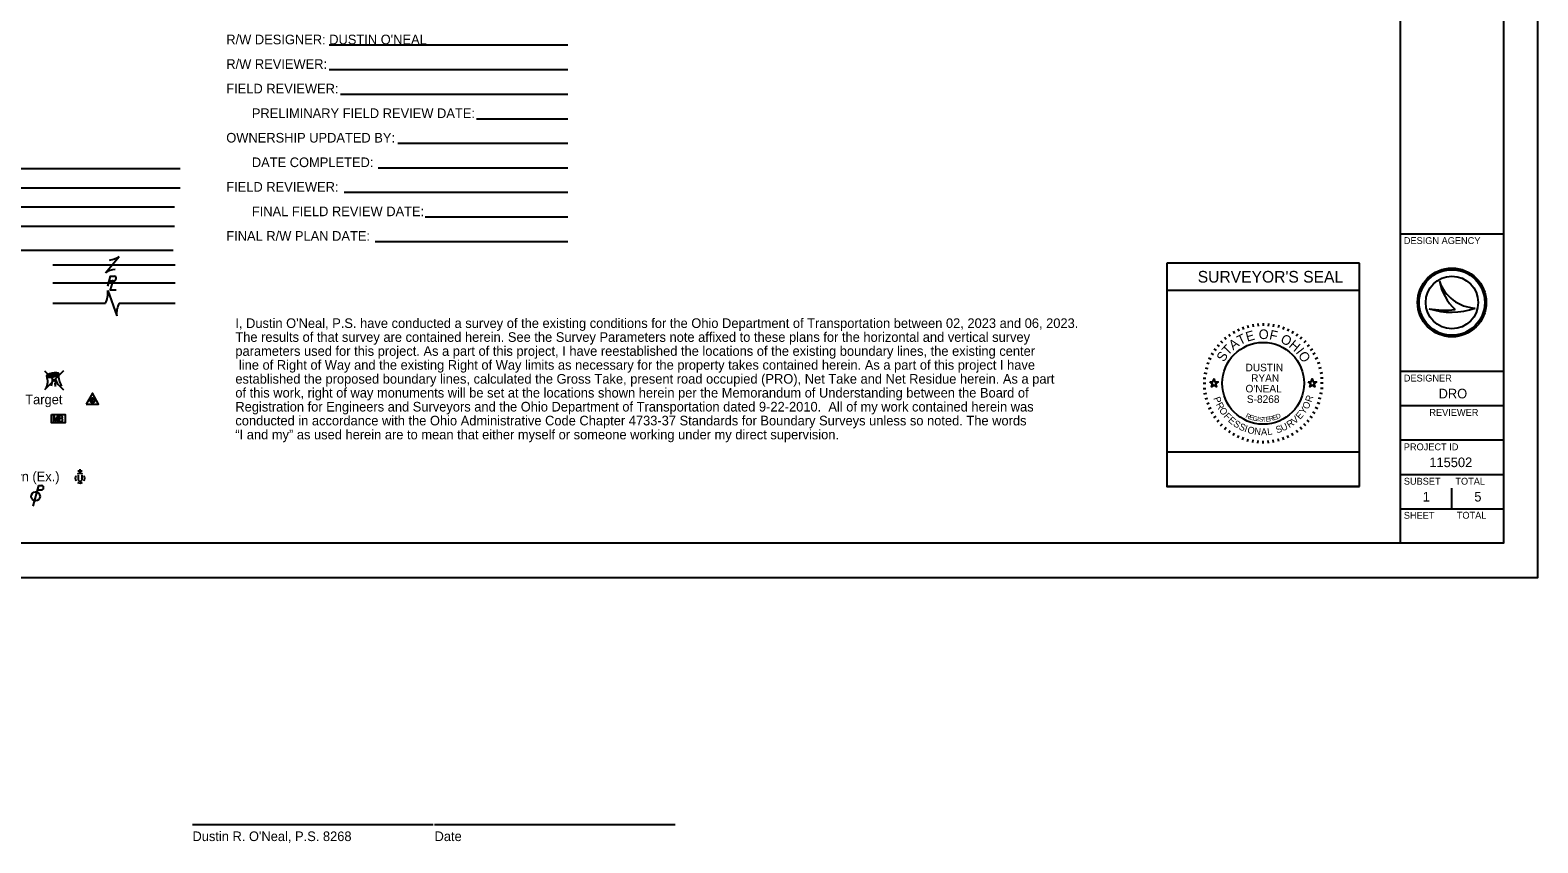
# Model space of a CAD drawing. Extents: x -11.1 to 34, y -3.9 to 22.
# Drawn here: x 12.07 to 34, y -3.86 to 7.96 of the extents above; entities that cross this region are included whole.
import ezdxf

# ---------------------------------------------------------------- set-up
doc = ezdxf.new("R2010")
doc.units = 0
for name, color, linetype in [('Default', 7, 'Continuous'), ('SH_Border', 7, 'Continuous'), ('SH_Cut_Line', 7, 'Continuous'), ('SH_Data', 7, 'Continuous'), ('SH_Text', 7, 'Continuous')]:
    doc.layers.add(name, color=color, linetype=linetype)

msp = doc.modelspace()

# ---------------------------------------------------------------- linework, layer by layer
at = {"layer": 'Default'}
for points in [[(29.227, 2.844), (29.274, 2.844), (29.289, 2.889), (29.303, 2.844), (29.35, 2.844), (29.312, 2.816), (29.327, 2.772), (29.289, 2.799), (29.251, 2.772), (29.265, 2.816)], [(30.657, 2.844), (30.704, 2.844), (30.719, 2.889), (30.733, 2.844), (30.78, 2.844), (30.742, 2.816), (30.757, 2.772), (30.719, 2.799), (30.681, 2.772), (30.695, 2.816)]]:
    msp.add_lwpolyline(points, close=True, dxfattribs=at)
at = {"layer": 'SH_Border'}
for p, q in [((32, 0.5), (32, 21.5)), ((32, 5), (33.5, 5)), ((32, 3), (33.5, 3)), ((32, 2.5), (33.5, 2.5)), ((32, 2), (33.5, 2)), ((32, 1.5), (33.5, 1.5)), ((32, 1), (33.5, 1))]:
    msp.add_line(p, q, dxfattribs=at)
msp.add_lwpolyline([(1.5, 21.5), (33.5, 21.5), (33.5, 0.5), (1.5, 0.5)], close=True, dxfattribs=at)
at = {"layer": 'SH_Cut_Line'}
msp.add_lwpolyline([(0, 0), (34, 0), (34, 22), (0, 22)], close=True, dxfattribs=at)
at = {"layer": 'SH_Data'}
for p, q in [((31.404, 4.574), (28.604, 4.574)), ((28.604, 4.574), (28.604, 1.324)), ((31.404, 1.324), (31.404, 4.574)), ((31.404, 4.174), (28.604, 4.174)), ((32.567, 4.31), (32.567, 4.31)), ((32.75, 4), (32.75, 4)), ((32.417, 3.91), (32.417, 3.91)), ((33.087, 3.919), (33.087, 3.919)), ((29.502, 3.541), (29.525, 3.508)), ((29.566, 3.582), (29.586, 3.547)), ((29.634, 3.617), (29.651, 3.581)), ((29.705, 3.646), (29.718, 3.609)), ((29.777, 3.669), (29.788, 3.631)), ((29.852, 3.686), (29.859, 3.646)), ((29.928, 3.696), (29.931, 3.656)), ((30.004, 3.699), (30.004, 3.659)), ((30.08, 3.696), (30.077, 3.656)), ((30.156, 3.686), (30.149, 3.646)), ((30.23, 3.669), (30.22, 3.631)), ((30.303, 3.646), (30.289, 3.609)), ((30.374, 3.617), (30.357, 3.581)), ((30.441, 3.582), (30.421, 3.547)), ((30.506, 3.541), (30.483, 3.508)), ((29.287, 3.326), (29.32, 3.303)), ((29.334, 3.386), (29.364, 3.361)), ((29.385, 3.443), (29.413, 3.414)), ((29.441, 3.494), (29.467, 3.464)), ((30.566, 3.494), (30.541, 3.464)), ((30.623, 3.443), (30.594, 3.414)), ((30.674, 3.386), (30.644, 3.361)), ((30.721, 3.326), (30.688, 3.303)), ((29.182, 3.123), (29.219, 3.11)), ((29.211, 3.194), (29.247, 3.177)), ((29.246, 3.262), (29.281, 3.242)), ((30.762, 3.262), (30.727, 3.242)), ((30.797, 3.194), (30.761, 3.177)), ((30.826, 3.123), (30.789, 3.11)), ((29.132, 2.9), (29.172, 2.897)), ((29.142, 2.976), (29.182, 2.969)), ((29.159, 3.051), (29.197, 3.04)), ((30.849, 3.051), (30.81, 3.04)), ((30.866, 2.976), (30.826, 2.969)), ((30.876, 2.9), (30.836, 2.897)), ((29.129, 2.824), (29.169, 2.824)), ((29.132, 2.748), (29.172, 2.751)), ((29.142, 2.672), (29.182, 2.679)), ((30.866, 2.672), (30.826, 2.679)), ((30.876, 2.748), (30.836, 2.751)), ((30.879, 2.824), (30.839, 2.824)), ((29.159, 2.598), (29.197, 2.608)), ((29.182, 2.525), (29.219, 2.538)), ((29.211, 2.454), (29.247, 2.471)), ((30.797, 2.454), (30.761, 2.471)), ((30.826, 2.525), (30.789, 2.538)), ((30.849, 2.598), (30.81, 2.608)), ((29.246, 2.387), (29.281, 2.407)), ((29.287, 2.322), (29.32, 2.345)), ((29.334, 2.262), (29.364, 2.287)), ((29.385, 2.205), (29.413, 2.234)), ((30.623, 2.205), (30.594, 2.234)), ((30.674, 2.262), (30.644, 2.287)), ((30.721, 2.322), (30.688, 2.345)), ((30.762, 2.387), (30.727, 2.407)), ((29.441, 2.154), (29.467, 2.184)), ((29.502, 2.107), (29.525, 2.14)), ((29.566, 2.066), (29.586, 2.101)), ((29.634, 2.031), (29.651, 2.067)), ((29.705, 2.002), (29.718, 2.039)), ((29.777, 1.979), (29.788, 2.017)), ((29.852, 1.962), (29.859, 2.002)), ((29.928, 1.952), (29.931, 1.992)), ((30.004, 1.949), (30.004, 1.989)), ((30.08, 1.952), (30.077, 1.992)), ((30.156, 1.962), (30.149, 2.002)), ((30.23, 1.979), (30.22, 2.017)), ((30.303, 2.002), (30.289, 2.039)), ((30.374, 2.031), (30.357, 2.067)), ((30.441, 2.066), (30.421, 2.101)), ((30.506, 2.107), (30.483, 2.14)), ((30.566, 2.154), (30.541, 2.184)), ((31.404, 1.324), (28.604, 1.324)), ((32.75, 1), (32.75, 1.3)), ((14.427, -3.594), (17.927, -3.594)), ((17.949, -3.594), (21.449, -3.594))]:
    msp.add_line(p, q, dxfattribs=at)
msp.add_lwpolyline([(31.404, 1.324), (31.404, 1.824), (28.604, 1.824), (28.604, 1.324)], close=True, dxfattribs=at)
for centre, radius in [((32.75, 4), 0.5), ((32.75, 4), 0.477), ((32.75, 4), 0.477), ((32.75, 4), 0.382), ((30.004, 2.824), 0.595)]:
    msp.add_circle(centre, radius, dxfattribs=at)
for centre, radius, start, end in [((33.116, 4.498), 0.58, 198.9257, 198.9319), ((33.347, 4.47), 0.796, 191.6379, 191.6421), ((33.116, 4.498), 0.58, 198.9319, 267.1657), ((33.347, 4.47), 0.796, 191.6421, 226.0947), ((32.739, 4.87), 1.013, 251.4576, 290.0832), ((32.648, 5.154), 1.266, 259.4964, 259.4995), ((32.739, 4.87), 1.013, 251.4527, 251.4576), ((32.648, 5.154), 1.266, 259.4995, 276.6672)]:
    msp.add_arc(centre, radius, start, end, dxfattribs=at)
at = {"layer": 'SH_Text'}
for p, q in [((16.415, 7.745), (19.888, 7.745)), ((16.415, 7.388), (19.888, 7.388)), ((16.58, 7.031), (19.888, 7.031)), ((18.561, 6.673), (19.888, 6.673)), ((17.416, 6.316), (19.888, 6.316)), ((10.765, 5.949), (14.249, 5.949)), ((17.13, 5.959), (19.888, 5.959)), ((10.765, 5.669), (14.249, 5.669)), ((16.633, 5.602), (19.888, 5.602)), ((10.265, 5.389), (14.165, 5.389)), ((10.265, 5.109), (14.165, 5.109)), ((17.814, 5.245), (19.888, 5.245)), ((17.085, 4.888), (19.888, 4.888)), ((9.797, 4.759), (14.147, 4.759)), ((13.16, 4.429), (13.36, 4.669)), ((12.395, 4.549), (14.177, 4.549)), ((13.26, 4.549), (13.26, 4.549)), ((12.395, 4.285), (14.177, 4.285)), ((13.195, 4.174), (13.325, 3.805)), ((13.218, 4.314), (13.283, 4.314)), ((13.258, 4.283), (13.258, 4.283)), ((12.395, 3.989), (13.16, 3.989)), ((13.26, 3.989), (13.26, 3.989)), ((13.36, 3.989), (14.177, 3.989)), ((12.274, 3.008), (12.552, 2.73)), ((12.552, 3.008), (12.274, 2.73)), ((12.413, 2.869), (12.413, 2.869)), ((12.413, 2.869), (12.413, 2.869)), ((12.474, 2.309), (12.474, 2.309)), ((12.823, 1.545), (12.759, 1.545)), ((12.791, 1.513), (12.791, 1.576)), ((12.187, 1.339), (12.107, 1.039)), ((12.187, 1.339), (12.23, 1.339)), ((12.764, 1.486), (12.764, 1.417)), ((12.791, 1.443), (12.791, 1.443)), ((12.818, 1.486), (12.818, 1.417)), ((12.17, 1.276), (12.23, 1.276))]:
    msp.add_line(p, q, dxfattribs=at)
for points in [[(13.197, 4.235), (13.236, 4.383), (13.288, 4.383)], [(13.271, 4.331), (13.232, 4.183), (13.319, 4.183)], [(12.409, 2.269), (12.409, 2.349), (12.438, 2.269), (12.466, 2.349), (12.466, 2.269)], [(12.525, 2.313), (12.528, 2.316), (12.53, 2.318), (12.531, 2.32), (12.532, 2.321), (12.533, 2.324), (12.534, 2.325), (12.535, 2.33), (12.535, 2.332), (12.535, 2.334), (12.534, 2.338), (12.533, 2.341), (12.531, 2.344), (12.528, 2.346), (12.526, 2.347), (12.524, 2.348), (12.521, 2.349), (12.49, 2.349), (12.49, 2.269), (12.525, 2.269), (12.529, 2.272), (12.533, 2.275), (12.536, 2.28), (12.538, 2.286), (12.539, 2.291), (12.539, 2.295), (12.538, 2.299), (12.535, 2.305), (12.532, 2.308), (12.525, 2.313), (12.49, 2.313)]]:
    msp.add_lwpolyline(points, dxfattribs=at)
for points in [[(12.882, 2.519), (13.062, 2.519), (12.972, 2.68)], [(12.374, 2.37), (12.574, 2.37), (12.574, 2.248), (12.374, 2.248)]]:
    msp.add_lwpolyline(points, close=True, dxfattribs=at)
for centre, radius in [((12.972, 2.577), 0.035), ((12.972, 2.577), 0.008), ((12.144, 1.179), 0.065)]:
    msp.add_circle(centre, radius, dxfattribs=at)
for centre, radius, start, end in [((13.202, 4.884), 0.267, 273.6945, 306.337), ((13.318, 4.214), 0.267, 93.6945, 126.337), ((12.863, 4.141), 0.334, 332.9422, 5.5848), ((13.283, 4.349), 0.0345, 270.471, 81.3281), ((13.657, 3.838), 0.334, 152.9422, 185.5848), ((12.121, 2.852), 0.2, 331.5338, 20.9269), ((12.137, 2.871), 0.253, 340.7938, 3.5481), ((12.738, 2.972), 0.316, 194.9653, 212.1216), ((12.693, 2.926), 0.215, 171.4106, 219.9194), ((12.608, 2.829), 0.182, 178.7926, 197.1224), ((12.23, 1.307), 0.0319, 268.8767, 91.1233), ((12.791, 1.443), 0.07, 150.0184, 209.9816), ((12.791, 1.443), 0.07, 60.0184, 120.0157), ((12.791, 1.443), 0.07, 239.9843, 299.9816), ((12.791, 1.43), 0.03, 205.1924, 334.8076), ((12.791, 1.443), 0.07, 330.0184, 29.9816)]:
    msp.add_arc(centre, radius, start, end, dxfattribs=at)
for major_axis in [(0.0868, 0.0187), (0.0651, 0.0141), (0.0488, 0.0105), (0.0275, 0.0059), (0.0154, 0.0033)]:
    msp.add_ellipse((12.394, 2.945), major_axis=major_axis, ratio=0.36865, dxfattribs=at)

# ---------------------------------------------------------------- texts
at = {"layer": 'Default'}
for s, p in [('SHEET', (32.05, 0.854)), ('TOTAL', (32.821, 0.855))]:
    msp.add_text(s, height=0.1, dxfattribs=at).set_placement(p)
at = {"layer": 'SH_Data'}
for s, height, p in [('DESIGN AGENCY', 0.1, (32.05, 4.85)), ("SURVEYOR'S SEAL", 0.17, (29.052, 4.289)), ('DUSTIN', 0.11, (29.747, 2.999)), ('RYAN', 0.11, (29.828, 2.846)), ('DESIGNER', 0.1, (32.05, 2.85)), ("O'NEAL", 0.11, (29.747, 2.692)), ('S-8268', 0.11, (29.767, 2.539)), ('DRO', 0.14, (32.556, 2.605)), ('REVIEWER', 0.1, (32.422, 2.35)), ('PROJECT ID', 0.1, (32.05, 1.85)), ('115502', 0.14, (32.421, 1.605)), ('SUBSET', 0.1, (32.05, 1.35)), ('TOTAL', 0.1, (32.8, 1.35)), ('1', 0.14, (32.325, 1.105)), ('5', 0.14, (33.076, 1.105))]:
    msp.add_text(s, height=height, dxfattribs=at).set_placement(p)
for s, height, rotation, p in [('T', 0.14, 25.7167, (29.666, 3.376)), ('E', 0.14, 15.7571, (29.772, 3.428)), ('O', 0.14, 359.7812, (29.939, 3.468)), ('F', 0.14, 347.4362, (30.085, 3.466)), ('O', 0.14, 332.2586, (30.244, 3.426)), ('T', 0.14, 46.4344, (29.492, 3.22)), ('A', 0.14, 36.4747, (29.567, 3.302)), ('H', 0.14, 319.9136, (30.367, 3.36)), ('I', 0.14, 308.367, (30.47, 3.272)), ('S', 0.14, 57.1924, (29.432, 3.125)), ('O', 0.14, 303.1491, (30.506, 3.233)), ('R', 0.1, 70.983, (30.705, 2.541)), ('P', 0.1, 289.7431, (29.279, 2.608)), ('R', 0.1, 296.9802, (29.313, 2.517)), ('O', 0.1, 304.7158, (29.357, 2.432)), ('E', 0.1, 48.2687, (30.54, 2.291)), ('Y', 0.1, 55.5058, (30.604, 2.364)), ('O', 0.1, 62.7428, (30.654, 2.437)), ('F', 0.1, 312.956, (29.423, 2.34)), ('E', 0.1, 319.6885, (29.485, 2.274)), ('S', 0.1, 326.9255, (29.559, 2.213)), ('S', 0.1, 334.1626, (29.64, 2.161)), ('I', 0.1, 341.3997, (29.723, 2.122)), ('R', 0.07, 334.487, (29.741, 2.329)), ('O', 0.1, 345.1351, (29.766, 2.106)), ('E', 0.07, 341.04, (29.795, 2.304)), ('G', 0.07, 347.4752, (29.845, 2.286)), ('I', 0.07, 353.7858, (29.913, 2.271)), ('S', 0.07, 356.8926, (29.94, 2.267)), ('T', 0.07, 3.0061, (29.99, 2.263)), ('E', 0.07, 6.0117, (30.043, 2.265)), ('R', 0.07, 11.9184, (30.096, 2.271)), ('E', 0.07, 17.6836, (30.154, 2.284)), ('D', 0.07, 23.3052, (30.205, 2.301)), ('S', 0.1, 18.3234, (30.204, 2.095)), ('U', 0.1, 25.5604, (30.287, 2.123)), ('R', 0.1, 33.296, (30.385, 2.171)), ('V', 0.1, 41.0316, (30.465, 2.225)), ('N', 0.1, 353.3752, (29.87, 2.08)), ('A', 0.1, 1.1108, (29.973, 2.068)), ('L', 0.1, 8.3479, (30.07, 2.071))]:
    msp.add_text(s, height=height, rotation=rotation, dxfattribs=at).set_placement(p)
at = {"layer": 'SH_Text'}
for s, p in [("R/W DESIGNER: DUSTIN O'NEAL", (14.919, 7.755)), ('R/W REVIEWER:', (14.919, 7.398)), ('FIELD REVIEWER:', (14.919, 7.041)), ('PRELIMINARY FIELD REVIEW DATE:', (15.291, 6.683)), ('OWNERSHIP UPDATED BY:', (14.919, 6.326)), ('DATE COMPLETED:', (15.291, 5.969)), ('FIELD REVIEWER:', (14.919, 5.612)), ('FINAL FIELD REVIEW DATE:', (15.291, 5.255)), ('FINAL R/W PLAN DATE:', (14.919, 4.898)), ("I, Dustin O'Neal, P.S. have conducted a survey of the existing conditions for the Ohio Department of Transportation between 02, 2023 and 06, 2023.  ", (15.051, 3.629)), ('The results of that survey are contained herein. See the Survey Parameters note affixed to these plans for the horizontal and vertical survey ', (15.051, 3.427)), ('parameters used for this project. As a part of this project, I have reestablished the locations of the existing boundary lines, the existing center', (15.051, 3.224)), (' line of Right of Way and the existing Right of Way limits as necessary for the property takes contained herein. As a part of this project I have ', (15.051, 3.022)), ('established the proposed boundary lines, calculated the Gross Take, present road occupied (PRO), Net Take and Net Residue herein. As a part ', (15.051, 2.819)), ('Wetland (Pr)         , Grass (Pr)            , Aerial Target    ', (8.249, 2.519)), ('of this work, right of way monuments will be set at the locations shown herein per the Memorandum of Understanding between the Board of ', (15.051, 2.617)), ('Registration for Engineers and Surveyors and the Ohio Department of Transportation dated 9-22-2010.  All of my work contained herein was ', (15.051, 2.414)), ('conducted in accordance with the Ohio Administrative Code Chapter 4733-37 Standards for Boundary Surveys unless so noted. The words ', (15.051, 2.212)), ('“I and my” as used herein are to mean that either myself or someone working under my direct supervision.', (15.051, 2.009)), ('Water Valve (Ex)         , Utility Valve Unknown (Ex.)', (8.249, 1.399)), ("Dustin R. O'Neal, P.S. 8268", (14.427, -3.834)), ('Date', (17.949, -3.834))]:
    msp.add_text(s, height=0.14, dxfattribs=at).set_placement(p)

doc.saveas('drawing.dxf')
